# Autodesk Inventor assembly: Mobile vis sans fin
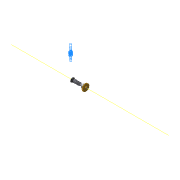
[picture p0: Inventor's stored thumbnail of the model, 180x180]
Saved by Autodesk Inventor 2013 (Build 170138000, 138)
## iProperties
Created: 2011-07
Part Number: Mobile vis sans fin
Document SubType Name: Assembly
Designer: Laur
Author: Laur
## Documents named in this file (6)
- D:\_an13-14\FORMULAIRE_2014\Sujet E4 Poissy 2014\Modélisation_7970_shimano_2014\Mobile vis sans fin.iam
- D:\_an13-14\FORMULAIRE_2014\Sujet E4 Poissy 2014\Modélisation_7970_shimano_2014\pièces mobile vis sans fin\vis sans fin arbrée.iam
- D:\_an13-14\FORMULAIRE_2014\Sujet E4 Poissy 2014\Modélisation_7970_shimano_2014\éléments standards\PARTserver35515621\WA673SSA.iam
- D:\_an13-14\FORMULAIRE_2014\Sujet E4 Poissy 2014\Modélisation_7970_shimano_2014\éléments standards\PARTserver35516212\RA144ZZA.iam
- D:\_an13-14\FORMULAIRE_2014\Sujet E4 Poissy 2014\Modélisation_7970_shimano_2014\Roue droite 43 dents module 0,3.ipt
- D:\_an13-14\FORMULAIRE_2014\Sujet E4 Poissy 2014\Modélisation_7970_shimano_2014\Roue codeuse.ipt
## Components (5 placed, 5 different names)
1. vis sans fin arbrée:1 [sub-assembly] — coaxialité  rlt 673 / arbre, pos. axiale rlt 673 / arbre, coaxialité rlt 144 / arbre, pos. axiale rlt 144 / arbre, Placage:5, Placage:6, Placage:7, Angle:1
2. WA673SSA:1 [sub-assembly] — coaxialité  rlt 673 / arbre, pos. axiale rlt 673 / arbre
3. RA144ZZA:1 [sub-assembly] — coaxialité rlt 144 / arbre, pos. axiale rlt 144 / arbre
4. Roue droite 43 dents module 0,3:1 — Placage:5, Placage:6
5. Roue codeuse:1 — Affleurement:1, Angle:1
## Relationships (9: Mate 7, Flush 1, Angle 1)
- coaxialité  rlt 673 / arbre [Mate]: vis sans fin arbrée:1 ↔ WA673SSA:1
- pos. axiale rlt 673 / arbre [Mate]: vis sans fin arbrée:1 ↔ WA673SSA:1
- coaxialité rlt 144 / arbre [Mate]: vis sans fin arbrée:1 ↔ RA144ZZA:1
- pos. axiale rlt 144 / arbre [Mate]: vis sans fin arbrée:1 ↔ RA144ZZA:1
- Placage:5 [Mate]: vis sans fin arbrée:1 ↔ Roue droite 43 dents module 0,3:1
- Placage:6 [Mate]: vis sans fin arbrée:1 ↔ Roue droite 43 dents module 0,3:1
- Affleurement:1 [Flush]: Roue codeuse:1
- Placage:7 [Mate]: vis sans fin arbrée:1
- Angle:1: vis sans fin arbrée:1 ↔ Roue codeuse:1
